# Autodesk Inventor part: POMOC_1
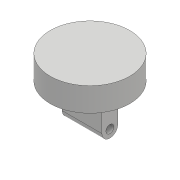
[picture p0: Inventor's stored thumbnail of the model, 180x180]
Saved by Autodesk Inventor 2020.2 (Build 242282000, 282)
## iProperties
Created: 2018-01
Part Number: POMOC_1
Material: Ogólne
Document SubType Name: Modeling
Designer: F.Stasiak
Density: 1 g/cm^3
Appearance: Domyślne
Manager: www.cadconsulting.pl
Company: Fabian Stasiak CAD Consulting
Author: F.Stasiak
Subject: Zbiór ćwiczeń. Autodesk Inventor 2020. Kurs podstawowy
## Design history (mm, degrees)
sketch "Szkic1"
  geometry: C1 r 50 at (0, 0); 1 further point
  constraints: 1 centre point, 1 coincident
  dimensions: "d0" = 100 diameter of C1
extrude "Wyciągnięcie proste1" new body sketch "Szkic1" distance "d1" = 30; taper "d2" = 0 deg
sketch "Szkic2"
  geometry: L1 (-25, 10)-(25, 10); L2 (25, 10)-(25, -10); L3 (25, -10)-(-25, -10); L4 (-25, -10)-(-25, 10); L5 (-25, 10)-(25, -10); L6 (25, 10)-(-25, -10); C1 r 50 at (0, 0) reference
  constraints: 12 end point, 2 equal length, 2 midpoint, 1 parallel, 1 vertical
  dimensions: "d3" = 50 distance of L2.end L3.end; "d4" = 20 distance of L1.end L2.end
extrude "Wyciągnięcie proste2" join sketch "Szkic2" distance "d5" = 50; taper "d6" = 0 deg
fillet "Zaokrąglenie1" dims "d7" = 10
hole "Otwór1" diameter "d10" = 10; stored, may be unused: countersink angle "d14" = 90 deg, drill point angle "d16" = 118 deg; dims "d8" = 10, "d9" = 10, "d11" = 6, "d12" = 4, "d13" = 2, "d15" = 8
node "Bryła1"
